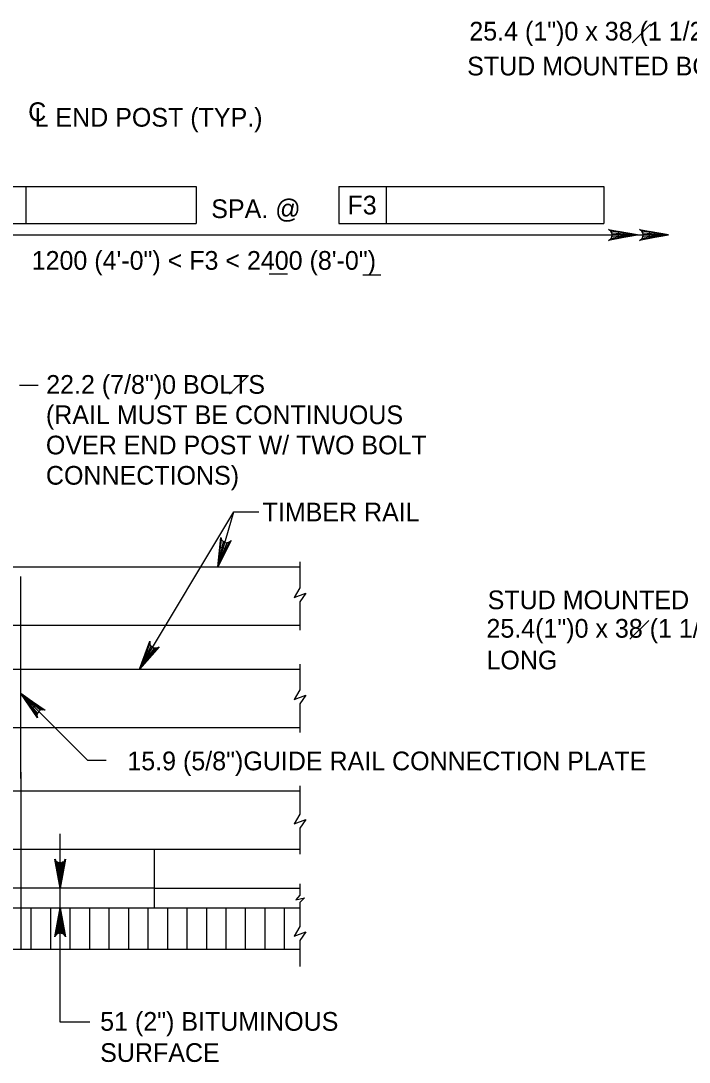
# Model space of a CAD drawing. Extents: x 0 to 36.3, y -66 to 0.
# Drawn here: x 8.89 to 13.18, y -16.23 to -9.55 of the extents above; entities that cross this region are included whole.
import ezdxf

# ---------------------------------------------------------------- set-up
doc = ezdxf.new("R2010")
doc.units = 0
for name, color, linetype in [('2', 7, 'Continuous'), ('3', 7, 'Continuous'), ('5', 7, 'Continuous')]:
    doc.layers.add(name, color=color, linetype=linetype)

msp = doc.modelspace()

# ---------------------------------------------------------------- linework, layer by layer
at = {"layer": '2'}
for p, q in [((10.6802, -13.0173), (10.6802, -13.1829)), ((7.1347, -13.0486), (9.1816, -13.0486)), ((9.1816, -13.0486), (10.6802, -13.0486)), ((10.6802, -13.1829), (10.6429, -13.2448)), ((10.6429, -13.2448), (10.7171, -13.217)), ((10.7171, -13.217), (10.6802, -13.2727)), ((10.6802, -13.2727), (10.6802, -13.4548)), ((7.1347, -13.4236), (8.8898, -13.4236)), ((8.8898, -13.4236), (10.6802, -13.4236)), ((10.6802, -13.6736), (10.6802, -13.8392)), ((7.1347, -13.7047), (8.8898, -13.7047)), ((8.8898, -13.7047), (10.6802, -13.7047)), ((10.6802, -13.8392), (10.6429, -13.9011)), ((10.6429, -13.9011), (10.7171, -13.8732)), ((10.7171, -13.8732), (10.6802, -13.9289)), ((10.6802, -13.9289), (10.6802, -14.1111)), ((7.3222, -14.0797), (8.8898, -14.0797)), ((8.8898, -14.0797), (10.6802, -14.0797)), ((8.8898, -14.3656), (8.8898, -14.4861)), ((4.8531, -14.4861), (10.6802, -14.4861)), ((8.8898, -14.4697), (8.8898, -14.5355)), ((8.8898, -14.4861), (8.8898, -15.5017)), ((10.6802, -14.4547), (10.6802, -14.6367)), ((10.6802, -14.6367), (10.6429, -14.6987)), ((10.6429, -14.6987), (10.7171, -14.6708)), ((10.7171, -14.6708), (10.6802, -14.7265)), ((10.6802, -14.7265), (10.6802, -14.8922)), ((4.8531, -14.861), (10.6802, -14.861)), ((9.7442, -14.861), (9.7442, -15.236)), ((10.6802, -15.083), (10.6802, -15.1568)), ((9.7442, -15.111), (10.6802, -15.111)), ((10.6802, -15.1568), (10.6543, -15.1847)), ((10.6543, -15.1847), (10.709, -15.1734)), ((10.709, -15.1734), (10.6802, -15.2033)), ((10.6802, -15.2033), (10.6802, -15.236)), ((4.8531, -15.236), (10.6802, -15.236)), ((10.6802, -15.2357), (10.6802, -15.3577)), ((10.6802, -15.236), (10.6802, -15.2444)), ((10.6802, -15.3577), (10.6429, -15.4196)), ((10.6429, -15.4196), (10.7171, -15.3918)), ((10.7171, -15.3918), (10.6802, -15.4474)), ((4.8531, -15.5017), (10.6802, -15.5017)), ((10.6802, -15.4474), (10.6802, -15.6132))]:
    msp.add_line(p, q, dxfattribs=at)
at = {"layer": '3'}
for p, q in [((12.8107, -9.6862), (12.9299, -9.567)), ((8.6203, -10.6093), (8.9227, -10.6093)), ((8.9227, -10.6093), (8.9227, -10.8455)), ((8.9227, -10.6093), (10.0156, -10.6093)), ((10.0156, -10.6093), (10.0156, -10.8455)), ((10.9298, -10.6093), (11.2323, -10.6093)), ((10.9298, -10.6093), (10.9298, -10.8455)), ((11.2323, -10.6093), (11.2323, -10.8455)), ((11.2323, -10.6093), (12.6306, -10.6093)), ((12.6306, -10.6093), (12.6306, -10.8455)), ((8.6203, -10.8455), (10.0156, -10.8455)), ((10.9298, -10.8455), (12.6306, -10.8455)), ((8.5148, -10.9191), (13.045, -10.9191)), ((10.4833, -11.1684), (10.5996, -11.1684)), ((11.0829, -11.1743), (11.1993, -11.1743)), ((10.2291, -11.9418), (10.3504, -11.8204)), ((8.8816, -11.8824), (9.0016, -11.8824)), ((9.6506, -13.7047), (10.2553, -12.6965)), ((10.1534, -13.0486), (10.2553, -12.6965)), ((10.2553, -12.6965), (10.3803, -12.6965)), ((10.2553, -12.6965), (10.4172, -12.6965)), ((8.8898, -14.4072), (8.8898, -13.1111)), ((12.797, -13.5137), (12.9183, -13.3923)), ((8.8898, -13.8617), (9.3165, -14.2905)), ((9.3165, -14.2905), (9.4365, -14.2905)), ((9.1421, -15.9711), (9.1421, -14.7624)), ((9.7442, -15.111), (4.5488, -15.111)), ((8.9571, -15.5017), (8.9571, -15.236)), ((9.0821, -15.5017), (9.0821, -15.236)), ((9.2071, -15.5017), (9.2071, -15.236)), ((9.3321, -15.5017), (9.3321, -15.236)), ((9.457, -15.5017), (9.457, -15.236)), ((9.582, -15.5017), (9.582, -15.236)), ((9.707, -15.5017), (9.707, -15.236)), ((9.832, -15.5017), (9.832, -15.236)), ((9.957, -15.5017), (9.957, -15.236)), ((10.082, -15.5017), (10.082, -15.236)), ((10.207, -15.5017), (10.207, -15.236)), ((10.332, -15.5017), (10.332, -15.236)), ((10.457, -15.5017), (10.457, -15.236)), ((10.582, -15.5017), (10.582, -15.236)), ((9.3325, -15.9711), (9.1421, -15.9711))]:
    msp.add_line(p, q, dxfattribs=at)
for points in [[(12.7214, -10.8982), (12.7214, -10.9399), (12.8464, -10.9191)], [(12.92, -10.8982), (12.92, -10.9399), (13.045, -10.9191)], [(10.2082, -12.9342), (10.1681, -12.9227), (10.1533, -13.0486)], [(9.7327, -13.6083), (9.697, -13.5869), (9.6506, -13.7047)], [(8.9603, -13.9609), (8.9887, -13.9328), (8.8898, -13.8617)]]:
    msp.add_lwpolyline(points, close=True, dxfattribs=at)
for points in [[(10.1534, -13.0486), (10.1717, -12.8598), (10.1772, -12.8763), (10.1872, -12.8869), (10.1986, -12.8925), (10.2112, -12.8939), (10.2252, -12.8902), (10.2388, -12.8792), (10.1534, -13.0486), (10.2252, -12.8902), (10.2112, -12.8939), (10.1534, -13.0486), (10.1986, -12.8925), (10.1872, -12.8869), (10.1534, -13.0486), (10.1772, -12.8763)], [(9.6506, -13.7047), (9.7165, -13.5269), (9.7177, -13.5443), (9.7246, -13.5572), (9.7342, -13.5654), (9.746, -13.57), (9.7605, -13.5701), (9.7764, -13.5628), (9.6506, -13.7047), (9.7605, -13.5701), (9.746, -13.57), (9.6506, -13.7047), (9.7342, -13.5654), (9.7246, -13.5572), (9.6506, -13.7047), (9.7177, -13.5443)], [(8.8898, -13.8617), (9.0461, -13.9692), (9.0289, -13.9661), (9.0148, -13.9697), (9.0044, -13.9769), (8.9971, -13.9872), (8.9935, -14.0013), (8.9966, -14.0185), (8.8898, -13.8617), (8.9935, -14.0013), (8.9971, -13.9872), (8.8898, -13.8617), (9.0044, -13.9769), (9.0148, -13.9697), (8.8898, -13.8617), (9.0289, -13.9661)], [(9.1421, -15.111), (9.1072, -14.9246), (9.1122, -14.9318), (9.1171, -14.939), (9.1234, -14.9427), (9.1296, -14.9464), (9.1359, -14.9474), (9.1421, -14.9485), (9.1484, -14.9474), (9.1546, -14.9464), (9.1609, -14.9427), (9.1671, -14.939), (9.1721, -14.9318), (9.1771, -14.9246), (9.1421, -15.111), (9.1721, -14.9318), (9.1671, -14.939), (9.1421, -15.111), (9.1609, -14.9427), (9.1546, -14.9464), (9.1421, -15.111), (9.1484, -14.9474), (9.1421, -14.9485), (9.1421, -15.111), (9.1359, -14.9474), (9.1296, -14.9464), (9.1421, -15.111), (9.1234, -14.9427), (9.1171, -14.939), (9.1421, -15.111), (9.1122, -14.9318)], [(9.1421, -15.236), (9.1771, -15.4224), (9.1721, -15.4152), (9.1671, -15.408), (9.1609, -15.4043), (9.1546, -15.4006), (9.1484, -15.3996), (9.1421, -15.3985), (9.1359, -15.3996), (9.1296, -15.4006), (9.1234, -15.4043), (9.1171, -15.408), (9.1122, -15.4152), (9.1072, -15.4224), (9.1421, -15.236), (9.1122, -15.4152), (9.1171, -15.408), (9.1421, -15.236), (9.1234, -15.4043), (9.1296, -15.4006), (9.1421, -15.236), (9.1359, -15.3996), (9.1421, -15.3985), (9.1421, -15.236), (9.1484, -15.3996), (9.1546, -15.4006), (9.1421, -15.236), (9.1609, -15.4043), (9.1671, -15.408), (9.1421, -15.236), (9.1721, -15.4152)]]:
    msp.add_lwpolyline(points, dxfattribs=at)
at = {"layer": '5'}
for points in [[(12.8464, -10.9191), (12.66, -10.954), (12.6743, -10.9441), (12.6817, -10.9316), (12.6839, -10.9191), (12.6817, -10.9066), (12.6743, -10.8941), (12.66, -10.8842), (12.8464, -10.9191), (12.6743, -10.8941), (12.6817, -10.9066), (12.8464, -10.9191), (12.6839, -10.9191), (12.6817, -10.9316), (12.8464, -10.9191), (12.6743, -10.9441)], [(13.045, -10.9191), (12.8586, -10.954), (12.8729, -10.9441), (12.8803, -10.9316), (12.8825, -10.9191), (12.8803, -10.9066), (12.8729, -10.8941), (12.8586, -10.8842), (13.045, -10.9191), (12.8729, -10.8941), (12.8803, -10.9066), (13.045, -10.9191), (12.8825, -10.9191), (12.8803, -10.9316), (13.045, -10.9191), (12.8729, -10.9441)]]:
    msp.add_lwpolyline(points, dxfattribs=at)

# ---------------------------------------------------------------- texts
at = {"layer": '3'}
for s, p in [('25.4 (1")0 x 38 (1 1/2")LONG', (11.7669, -9.6717)), ('STUD MOUNTED BOLTS', (11.7531, -9.8957)), ('C', (8.9368, -10.1883)), ('L END POST (TYP.)', (8.978, -10.2244)), ('SPA. @', (10.1113, -10.8111)), ('1200 (4\'-0") < F3 < 2400 (8\'-0")', (8.9593, -11.1427)), ('22.2 (7/8")0 BOLTS', (9.0525, -11.9385)), ('(RAIL MUST BE CONTINUOUS', (9.0507, -12.1332)), ('OVER END POST W/ TWO BOLT', (9.0507, -12.3274)), ('CONNECTIONS)', (9.0507, -12.5217)), ('TIMBER RAIL', (10.4406, -12.7573)), ('STUD MOUNTED BOLTS', (11.8845, -13.3208)), ('25.4(1")0 x 38 (1 1/2")', (11.8767, -13.5036)), ('LONG', (11.8767, -13.7069)), ('15.9 (5/8")GUIDE RAIL CONNECTION PLATE', (9.5732, -14.3544)), ('51 (2") BITUMINOUS', (9.3987, -16.0257)), ('SURFACE', (9.3987, -16.2257))]:
    msp.add_text(s, height=0.12, dxfattribs=at).set_placement(p)
msp.add_text('F3', height=0.12, rotation=359.93823, dxfattribs=at).set_placement((10.985, -10.7874))

doc.saveas('drawing.dxf')
